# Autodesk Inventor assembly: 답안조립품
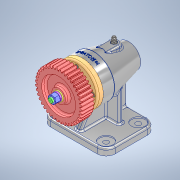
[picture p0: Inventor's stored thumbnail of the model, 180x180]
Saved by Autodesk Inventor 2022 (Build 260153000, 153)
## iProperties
Created: 2024-12
Part Number: 답안조립품
Document SubType Name: Assembly
Designer: PC-12
Author: PC-12
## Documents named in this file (15)
- C:\Users\PC-12\Desktop\741204V1016\답안조립품.iam
- C:\Users\PC-12\Desktop\741204V1016\본체.ipt
- C:\Users\PC-12\Desktop\741204V1016\가져온 구성요소\스퍼기어\스퍼기어.ipt
- C:\Users\PC-12\Desktop\741204V1016\가져온 구성요소\스프링 와셔 M8\스프링 와셔 M8.ipt
- C:\Users\PC-12\Desktop\741204V1016\가져온 구성요소\실링\실링.ipt
- C:\Users\PC-12\Desktop\741204V1016\가져온 구성요소\앵귤러 볼 베어링 7003A\앵귤러 볼 베어링 7003A.ipt
- C:\Users\PC-12\Desktop\741204V1016\가져온 구성요소\앵귤러 볼 제어링 7204A\앵귤러 볼 제어링 7204A.ipt
- C:\Users\PC-12\Desktop\741204V1016\가져온 구성요소\오일 실 20 32 8\오일 실 20 32 8.ipt
- C:\Users\PC-12\Desktop\741204V1016\가져온 구성요소\육각 너트 M8\육각 너트 M8.ipt
- C:\Users\PC-12\Desktop\741204V1016\가져온 구성요소\육각 소켓 머리 볼트 M4x10\육각 소켓 머리 볼트 M4x10.ipt
- C:\Users\PC-12\Desktop\741204V1016\가져온 구성요소\축\축.ipt
- C:\Users\PC-12\Desktop\741204V1016\가져온 구성요소\커버\커버.ipt
- C:\Users\PC-12\Desktop\741204V1016\가져온 구성요소\평와셔 M8\평와셔 M8.ipt
- C:\Users\PC-12\Desktop\741204V1016\가져온 구성요소\평행 키 4x4x14\평행 키 4x4x14.ipt
- C:\Users\PC-12\Desktop\741204V1016\가져온 구성요소\그리스 니플 M6x0.75\그리스 니플 M6x0.75.ipt
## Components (1 placed, 1 different names)
1. 그리스 니플 M6x0.75:1
